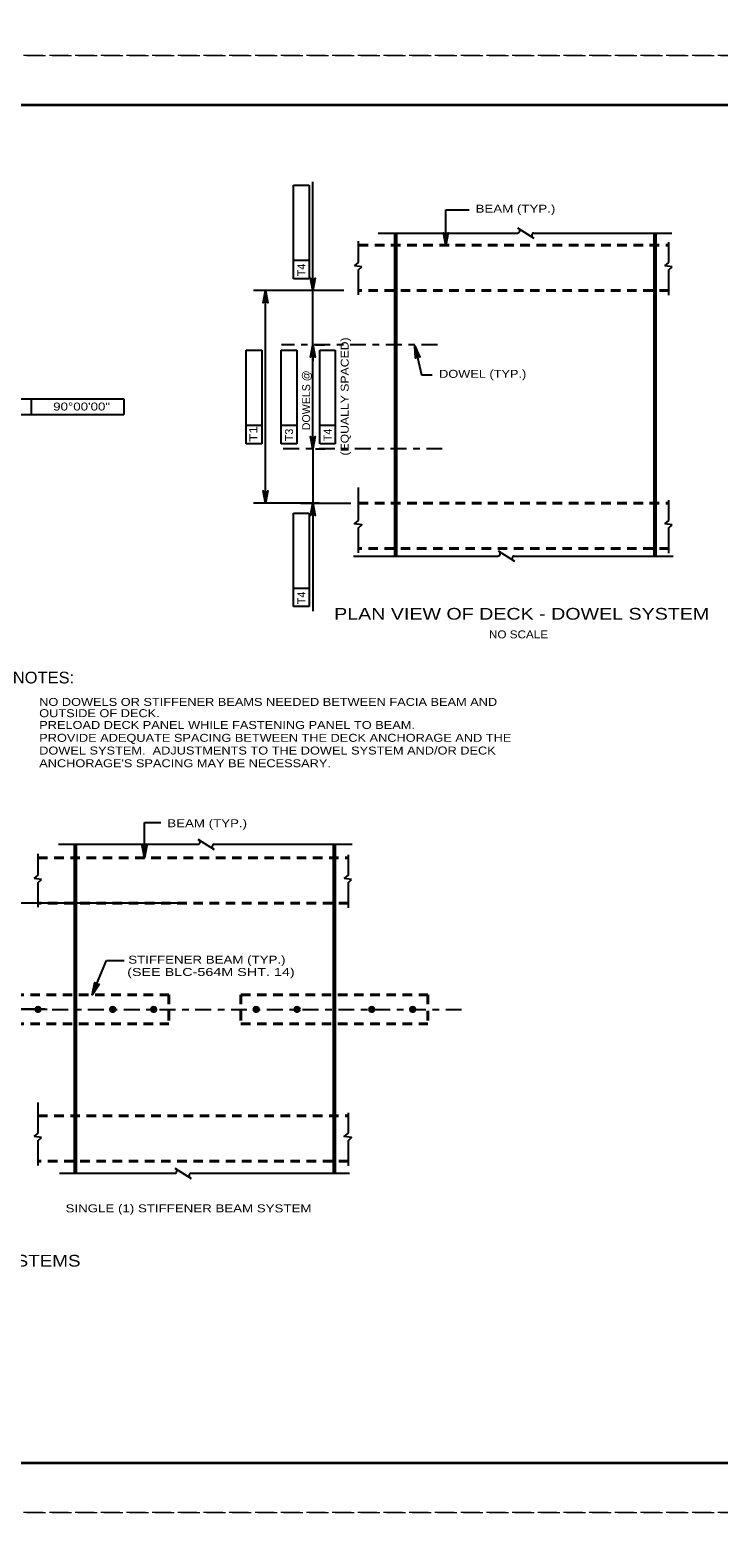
# Model space of a CAD drawing. Extents: x -11 to 79, y -154 to 0.
# Drawn here: x 49.19 to 59.58, y -110.38 to -87.62 of the extents above; entities that cross this region are included whole.
import ezdxf
from ezdxf.enums import TextEntityAlignment as Align

# ---------------------------------------------------------------- set-up
doc = ezdxf.new("R2010")
doc.units = 0
doc.header["$LTSCALE"] = 0.048
for name, pattern in [('DOT_DASHED', [7.7, 5, -1.2, 0.3, -1.2]), ('LONG_DASHED', [7.5, 6, -1.5]), ('MEDIUM_DASHED', [4.5, 3, -1.5])]:
    doc.linetypes.add(name, pattern=pattern)
for name, color, linetype, lineweight in [('1', 7, 'Continuous', 25), ('2', 7, 'Continuous', 35), ('3', 7, 'Continuous', 25), ('4', 7, 'Continuous', 25), ('63', 7, 'LONG_DASHED', 13)]:
    doc.layers.add(name, color=color, linetype=linetype, lineweight=lineweight)

msp = doc.modelspace()

# ---------------------------------------------------------------- hatches: boundary and pattern name
at = {"layer": '4'}
for points in [[(55.4595, -90.86675), (55.46075, -90.862), (55.45833, -90.862)], [(53.43225, -92.49133), (53.47225, -92.49133), (53.45225, -92.37133)], [(54.9915, -92.383), (54.99142, -92.38783), (54.99367, -92.38733)], [(50.91017, -100.11533), (50.91133, -100.11058), (50.90892, -100.11058)], [(50.12092, -102.18225), (50.12383, -102.17833), (50.12167, -102.17742)]]:
    msp.add_hatch(color=256, dxfattribs=at).paths.add_polyline_path(points)

# ---------------------------------------------------------------- linework, layer by layer
at = {"layer": '1', "lineweight": 35}
msp.add_lwpolyline([(35.75, -109.25), (67.25, -109.25), (67.25, -88.75), (35.75, -88.75)], close=True, dxfattribs=at)
at = {"layer": '2', "lineweight": 53}
for p, q in [((54.70658, -95.55908), (54.70658, -90.68192)), ((58.62, -95.55908), (58.62, -90.68192)), ((49.86867, -104.87733), (49.86867, -99.90983)), ((53.78208, -104.87733), (53.78208, -99.90983))]:
    msp.add_line(p, q, dxfattribs=at)
at = {"layer": '3'}
for p, q in [((54.14408, -91.12817), (54.14408, -90.80425)), ((54.43967, -90.68192), (56.54117, -90.68192)), ((56.54392, -90.6045), (56.79033, -90.75933)), ((56.78975, -90.68192), (58.87275, -90.68192)), ((58.827, -91.12817), (58.827, -90.81917)), ((54.0825, -91.17575), (54.14408, -91.12817)), ((54.19283, -91.19275), (54.0825, -91.17575)), ((54.14408, -91.2365), (54.19283, -91.19275)), ((54.14408, -91.61333), (54.14408, -91.2365)), ((58.76542, -91.17575), (58.827, -91.12817)), ((58.87575, -91.19275), (58.76542, -91.17575)), ((58.827, -91.2365), (58.87575, -91.19275)), ((58.827, -91.62083), (58.827, -91.2365)), ((54.70575, -92.40283), (54.70567, -92.33992)), ((58.62008, -92.40725), (58.62, -92.34433)), ((54.70575, -93.97233), (54.70567, -93.90942)), ((58.62008, -93.97683), (58.62, -93.91392)), ((54.14408, -95.02308), (54.14408, -94.52508)), ((58.827, -95.02308), (58.827, -94.71408)), ((58.76542, -95.07067), (58.827, -95.02308)), ((58.87567, -95.08758), (58.76542, -95.07067)), ((54.06583, -95.55908), (56.24517, -95.55908)), ((56.24792, -95.48167), (56.49433, -95.6365)), ((56.49375, -95.55908), (58.89108, -95.55908)), ((49.61367, -99.90983), (51.71517, -99.90983)), ((51.718, -99.83242), (51.96433, -99.98725)), ((51.96383, -99.90983), (54.04675, -99.90983)), ((49.30625, -100.37675), (49.30625, -100.05283)), ((49.24467, -100.42433), (49.30625, -100.37675)), ((49.35492, -100.44133), (49.24467, -100.42433)), ((49.30625, -100.48508), (49.35492, -100.44133)), ((49.30625, -100.86192), (49.30625, -100.48508)), ((54.03783, -100.44133), (53.9275, -100.42433)), ((53.98917, -100.48508), (54.03783, -100.44133)), ((53.98917, -100.86942), (53.98917, -100.48508)), ((49.30625, -104.12533), (49.30625, -103.80742)), ((49.30625, -104.272), (49.30625, -103.948)), ((53.98917, -104.272), (53.98917, -103.963)), ((49.24467, -104.3195), (49.30625, -104.272)), ((49.355, -104.3365), (49.24467, -104.3195)), ((49.30625, -104.38025), (49.355, -104.3365)), ((49.30625, -104.75717), (49.30625, -104.38025)), ((49.63058, -104.87733), (51.36725, -104.87733)), ((51.37, -104.79992), (51.61642, -104.95475)), ((51.61583, -104.87733), (54.008, -104.87733))]:
    msp.add_line(p, q, dxfattribs=at)
at = {"layer": '3', "linetype": 'MEDIUM_DASHED', "lineweight": 40}
for p, q in [((54.14408, -90.86675), (58.827, -90.86675)), ((58.827, -91.55167), (54.14408, -91.55167)), ((54.14408, -94.76158), (58.827, -94.76158)), ((58.827, -95.44658), (54.14408, -95.44658)), ((49.30625, -100.11533), (53.98917, -100.11533)), ((53.98917, -100.80025), (49.30625, -100.80025)), ((48.45733, -102.18225), (51.28017, -102.18225)), ((51.28017, -102.18225), (51.28017, -102.62325)), ((52.36725, -102.18225), (52.36725, -102.62325)), ((48.45733, -102.62325), (51.28017, -102.62325)), ((52.36725, -102.62325), (55.19008, -102.62325)), ((49.30625, -104.0105), (53.98917, -104.0105)), ((53.98917, -104.6955), (49.30625, -104.6955))]:
    msp.add_line(p, q, dxfattribs=at)
at = {"layer": '3', "linetype": 'DOT_DASHED'}
for p, q in [((55.33433, -92.37142), (52.97933, -92.37108)), ((55.407, -93.94092), (52.97875, -93.9405))]:
    msp.add_line(p, q, dxfattribs=at)
at = {"layer": '3'}
for points in [[(54.14408, -95.50825), (54.14408, -95.13133), (54.19283, -95.08758), (54.0825, -95.07067), (54.14408, -95.02308)], [(58.827, -95.51575), (58.827, -95.13133), (58.87567, -95.08758)], [(53.9275, -100.42433), (53.98917, -100.37675), (53.98917, -100.06775)], [(53.98917, -104.76467), (53.98917, -104.38025), (54.03792, -104.3365), (53.92758, -104.3195), (53.98917, -104.272)]]:
    msp.add_lwpolyline(points, dxfattribs=at)
at = {"layer": '3', "linetype": 'MEDIUM_DASHED', "lineweight": 40}
msp.add_lwpolyline([(52.36725, -102.18225), (55.19008, -102.18225), (55.19008, -102.62325)], dxfattribs=at)
at = {"layer": '3', "lineweight": 40}
for centre, radius in [((49.3057, -102.40274), 0.03333), ((49.3057, -102.40274), 0.02953), ((49.3057, -102.40274), 0.025), ((49.3057, -102.40274), 0.01667), ((49.3057, -102.40274), 0.00833), ((50.43168, -102.40274), 0.03333), ((50.43168, -102.40274), 0.02953), ((50.43168, -102.40274), 0.025), ((50.43168, -102.40274), 0.01667), ((50.43168, -102.40274), 0.00833), ((51.04979, -102.40274), 0.03333), ((51.04979, -102.40274), 0.02953), ((51.04979, -102.40274), 0.025), ((51.04979, -102.40274), 0.01667), ((51.04979, -102.40274), 0.00833), ((52.59751, -102.40274), 0.03333), ((52.59751, -102.40274), 0.025), ((52.59751, -102.40274), 0.01667), ((52.59751, -102.40274), 0.00833), ((53.21562, -102.40274), 0.03333), ((53.21562, -102.40274), 0.025), ((53.21562, -102.40274), 0.01667), ((53.21562, -102.40274), 0.00833), ((54.3416, -102.40274), 0.03333), ((54.3416, -102.40274), 0.025), ((54.3416, -102.40274), 0.01667), ((54.3416, -102.40274), 0.00833), ((54.95971, -102.40274), 0.03333), ((54.95971, -102.40274), 0.025), ((54.95971, -102.40274), 0.01667), ((54.95971, -102.40274), 0.00833)]:
    msp.add_circle(centre, radius, dxfattribs=at)
at = {"layer": '3'}
for centre in [(52.59751, -102.40274), (53.21562, -102.40274), (54.3416, -102.40274), (54.95971, -102.40274)]:
    msp.add_circle(centre, 0.02953, dxfattribs=at)
for centre, start, end in [((56.54116, -90.64551), 270, 60), ((56.79318, -90.7181), 95.32859, 237.86724), ((56.24514, -95.5227), 270, 60), ((56.49717, -95.59528), 95.32859, 237.86724), ((51.71516, -99.87345), 270, 60), ((51.96718, -99.94604), 95.32859, 237.86724), ((51.36718, -104.84096), 270, 60), ((51.61921, -104.91354), 95.32859, 237.86724)]:
    msp.add_arc(centre, 0.03637, start, end, dxfattribs=at)
at = {"layer": '4'}
for p, q in [((53.45225, -91.31117), (53.45225, -89.90783)), ((53.161, -89.96025), (53.39725, -89.96025)), ((53.161, -91.09667), (53.161, -89.96025)), ((53.39725, -89.96025), (53.39725, -91.37225)), ((55.4595, -90.86675), (55.4595, -90.33325)), ((55.4595, -90.33325), (55.81133, -90.33325)), ((53.161, -91.37225), (53.161, -91.09667)), ((53.39725, -91.09667), (53.161, -91.09667)), ((53.39725, -91.37225), (53.161, -91.37225)), ((53.45225, -92.37117), (53.45225, -91.31117)), ((53.92108, -91.55167), (52.55692, -91.55167)), ((52.73692, -94.7615), (52.73692, -91.55167)), ((53.39017, -91.55117), (53.27225, -91.55117)), ((53.45225, -93.94083), (53.45225, -92.37133)), ((53.49433, -92.37133), (53.63225, -92.37133)), ((54.9915, -92.383), (55.09475, -92.82175)), ((52.44575, -92.44992), (52.682, -92.44992)), ((52.44575, -93.58633), (52.44575, -92.44992)), ((52.682, -92.44992), (52.682, -93.86192)), ((52.97433, -93.86192), (52.97433, -92.44992)), ((52.97433, -92.44992), (53.2105, -92.44992)), ((53.2105, -92.44992), (53.2105, -93.86192)), ((53.45225, -92.49133), (53.45225, -92.61133)), ((53.55575, -92.44992), (53.79192, -92.44992)), ((53.55575, -93.58633), (53.55575, -92.44992)), ((53.79192, -92.44992), (53.79192, -93.86192)), ((55.09475, -92.82175), (55.25558, -92.82175)), ((48.89983, -93.183), (50.60067, -93.183)), ((49.20233, -93.183), (49.20233, -93.41925)), ((50.60067, -93.183), (50.60067, -93.41925)), ((48.89983, -93.41925), (50.60067, -93.41925)), ((52.44575, -93.86192), (52.44575, -93.58633)), ((52.682, -93.58633), (52.44575, -93.58633)), ((53.2105, -93.58633), (52.97433, -93.58633)), ((53.45225, -93.82083), (53.45225, -93.70083)), ((53.55575, -93.86192), (53.55575, -93.58633)), ((53.79192, -93.58633), (53.55575, -93.58633)), ((52.682, -93.86192), (52.44575, -93.86192)), ((53.2105, -93.86192), (52.97433, -93.86192)), ((53.45225, -93.94075), (53.45225, -96.38892)), ((53.49358, -93.94075), (53.63225, -93.94075)), ((53.79192, -93.86192), (53.55575, -93.86192)), ((53.54633, -94.7615), (52.55692, -94.7615)), ((53.161, -96.32275), (53.161, -94.91067)), ((53.161, -94.91067), (53.39725, -94.91067)), ((53.26525, -94.76133), (54.02392, -94.76158)), ((53.50658, -94.76142), (53.27225, -94.76142)), ((53.39725, -94.91067), (53.39725, -96.32275)), ((53.45225, -94.88142), (53.45225, -95.00142)), ((53.39725, -96.04708), (53.161, -96.04708)), ((53.39725, -96.32275), (53.161, -96.32275)), ((50.91017, -100.11533), (50.91017, -99.58183)), ((50.91017, -99.58183), (51.15892, -99.58183)), ((49.40525, -100.80025), (47.02308, -100.80025)), ((51.42308, -100.80025), (47.72342, -100.80025)), ((50.12092, -102.18225), (50.33825, -101.66358)), ((50.33817, -101.66358), (50.60583, -101.66358)), ((47.65867, -102.40158), (49.44058, -102.40158)), ((49.40525, -102.40158), (47.72342, -102.40158))]:
    msp.add_line(p, q, dxfattribs=at)
at = {"layer": '4', "linetype": 'DOT_DASHED'}
msp.add_line((49.51892, -102.40275), (55.7065, -102.40275), dxfattribs=at)
at = {"layer": '4'}
for points in [[(55.4595, -90.86675), (55.42458, -90.68033), (55.4345, -90.69467), (55.447, -90.70208), (55.4595, -90.70425), (55.472, -90.70208), (55.4845, -90.69467), (55.49442, -90.68033), (55.4595, -90.86675), (55.4845, -90.69467), (55.472, -90.70208), (55.4595, -90.86675), (55.4595, -90.70425), (55.447, -90.70208), (55.4595, -90.86675), (55.4345, -90.69467)], [(53.45225, -91.55167), (53.41733, -91.36525), (53.42725, -91.37958), (53.43975, -91.387), (53.45225, -91.38917), (53.46475, -91.387), (53.47725, -91.37958), (53.48717, -91.36525), (53.45225, -91.55167), (53.47725, -91.37958), (53.46475, -91.387), (53.45225, -91.55167), (53.45225, -91.38917), (53.43975, -91.387), (53.45225, -91.55167), (53.42725, -91.37958)], [(52.73692, -91.55167), (52.77183, -91.73808), (52.76192, -91.72375), (52.74942, -91.71633), (52.73692, -91.71417), (52.72442, -91.71633), (52.71192, -91.72375), (52.702, -91.73808), (52.73692, -91.55167), (52.71192, -91.72375), (52.72442, -91.71633), (52.73692, -91.55167), (52.73692, -91.71417), (52.74942, -91.71633), (52.73692, -91.55167), (52.76192, -91.72375)], [(53.45225, -92.37117), (53.48717, -92.55758), (53.47725, -92.54317), (53.46475, -92.53583), (53.45225, -92.53367), (53.43975, -92.53583), (53.42725, -92.54317), (53.41733, -92.55758), (53.45225, -92.37117), (53.42725, -92.54317), (53.43975, -92.53583), (53.45225, -92.37117), (53.45225, -92.53367), (53.46475, -92.53583), (53.45225, -92.37117), (53.47725, -92.54317)], [(54.9915, -92.383), (55.06825, -92.55642), (55.05525, -92.54475), (55.04142, -92.54042), (55.02875, -92.54117), (55.01708, -92.54617), (55.00658, -92.55617), (55.00017, -92.5725), (54.9915, -92.383), (55.00658, -92.55617), (55.01708, -92.54617), (54.9915, -92.383), (55.02875, -92.54117), (55.04142, -92.54042), (54.9915, -92.383), (55.05525, -92.54475)], [(53.45225, -93.94058), (53.41733, -93.75417), (53.42725, -93.7685), (53.43975, -93.77592), (53.45225, -93.77808), (53.46475, -93.77592), (53.47725, -93.7685), (53.48717, -93.75417), (53.45225, -93.94058), (53.47725, -93.7685), (53.46475, -93.77592), (53.45225, -93.94058), (53.45225, -93.77808), (53.43975, -93.77592), (53.45225, -93.94058), (53.42725, -93.7685)], [(52.73692, -94.7615), (52.702, -94.57508), (52.71192, -94.58942), (52.72442, -94.59683), (52.73692, -94.599), (52.74942, -94.59683), (52.76192, -94.58942), (52.77183, -94.57508), (52.73692, -94.7615), (52.76192, -94.58942), (52.74942, -94.59683), (52.73692, -94.7615), (52.73692, -94.599), (52.72442, -94.59683), (52.73692, -94.7615), (52.71192, -94.58942)], [(53.45225, -94.76142), (53.48717, -94.94783), (53.47725, -94.93342), (53.46475, -94.926), (53.45225, -94.92392), (53.43975, -94.926), (53.42725, -94.93342), (53.41733, -94.94783), (53.45225, -94.76142), (53.42725, -94.93342), (53.43975, -94.926), (53.45225, -94.76142), (53.45225, -94.92392), (53.46475, -94.926), (53.45225, -94.76142), (53.47725, -94.93342)], [(50.91017, -100.11533), (50.87525, -99.92892), (50.88517, -99.94325), (50.89767, -99.95067), (50.91017, -99.95283), (50.92267, -99.95067), (50.93517, -99.94325), (50.94508, -99.92892), (50.91017, -100.11533), (50.93517, -99.94325), (50.92267, -99.95067), (50.91017, -100.11533), (50.91017, -99.95283), (50.89767, -99.95067), (50.91017, -100.11533), (50.88517, -99.94325)], [(50.12092, -102.18225), (50.16075, -101.99683), (50.16433, -102.01392), (50.173, -102.02558), (50.18375, -102.03242), (50.19608, -102.03525), (50.2105, -102.03325), (50.22517, -102.02383), (50.12092, -102.18225), (50.2105, -102.03325), (50.19608, -102.03525), (50.12092, -102.18225), (50.18375, -102.03242), (50.173, -102.02558), (50.12092, -102.18225), (50.16433, -102.01392)]]:
    msp.add_lwpolyline(points, dxfattribs=at)
for points in [[(55.4595, -90.86675), (55.46075, -90.862), (55.45833, -90.862)], [(53.43225, -92.49133), (53.47225, -92.49133), (53.45225, -92.37133)], [(54.9915, -92.383), (54.99142, -92.38783), (54.99367, -92.38733)], [(50.91017, -100.11533), (50.91133, -100.11058), (50.90892, -100.11058)], [(50.12092, -102.18225), (50.12383, -102.17833), (50.12167, -102.17742)]]:
    msp.add_lwpolyline(points, close=True, dxfattribs=at)
at = {"layer": '63'}
for points in [[(34, -88), (68, -88), (68, -66), (34, -66)], [(34, -110), (68, -110), (68, -88), (34, -88)], [(34, -132), (68, -132), (68, -110), (34, -110)]]:
    msp.add_lwpolyline(points, close=True, dxfattribs=at)

# ---------------------------------------------------------------- texts
at = {"layer": '4'}
for s, height, width, p in [('BEAM (TYP.)', 0.12, 1.25, (55.90933, -90.37442)), ('DOWEL (TYP.)', 0.12, 1.2, (55.35858, -92.868)), ('NO SCALE', 0.12, 1.1, (56.11075, -96.80117)), ('NOTES:', 0.1772, 1.05, (48.924, -97.48167)), ('OUTSIDE OF DECK.', 0.12, 1.2, (49.32283, -97.99092)), ('NO DOWELS OR STIFFENER BEAMS NEEDED BETWEEN FACIA BEAM AND ', 0.12, 1.2, (49.32283, -97.82092)), ('PRELOAD DECK PANEL WHILE FASTENING PANEL TO BEAM.', 0.12, 1.2, (49.32283, -98.169)), ('PROVIDE ADEQUATE SPACING BETWEEN THE DECK ANCHORAGE AND THE ', 0.12, 1.2, (49.32283, -98.36292)), ('DOWEL SYSTEM.  ADJUSTMENTS TO THE DOWEL SYSTEM AND/OR DECK', 0.12, 1.2, (49.32283, -98.55483)), ("ANCHORAGE'S SPACING MAY BE NECESSARY.", 0.12, 1.2, (49.32283, -98.74675)), ('BEAM (TYP.)', 0.12, 1.25, (51.25625, -99.65233)), ('STIFFENER BEAM (TYP.)', 0.12, 1.25, (50.66667, -101.712)), ('(SEE BLC-564M SHT. 14)', 0.12, 1.35, (50.65058, -101.89808))]:
    msp.add_text(s, height=height, dxfattribs=dict(at, width=width)).set_placement(p)
for s, p in [('T4', (53.34008, -91.23979)), ('DOWELS @', (53.41225, -93.20775)), ('T3', (53.15333, -93.72971)), ('T4', (53.73475, -93.72946)), ('T4', (53.34008, -96.19029))]:
    msp.add_text(s, height=0.12, rotation=90, dxfattribs=at).set_placement(p, align=Align.CENTER)
for s, width, p in [('(EQUALLY SPACED)', 1.15, (53.99367, -93.14979)), ('T1', 1.3, (52.61433, -93.71537))]:
    msp.add_text(s, height=0.12, rotation=90, dxfattribs=dict(at, width=width)).set_placement(p, align=Align.CENTER)
for s, height, width, p in [('90°00\'00"', 0.12, 1.25, (49.96304, -93.36117)), ('PLAN VIEW OF DECK - DOWEL SYSTEM', 0.1772, 1.25, (56.60492, -96.51908)), ('SINGLE (1) STIFFENER BEAM SYSTEM', 0.12, 1.25, (51.57625, -105.46658)), ('PLAN VIEWS OF ALTERNATE STIFFENER BEAM SYSTEMS', 0.1772, 1.2, (45.97279, -106.28583))]:
    msp.add_text(s, height=height, dxfattribs=dict(at, width=width)).set_placement(p, align=Align.CENTER)

doc.saveas('drawing.dxf')
